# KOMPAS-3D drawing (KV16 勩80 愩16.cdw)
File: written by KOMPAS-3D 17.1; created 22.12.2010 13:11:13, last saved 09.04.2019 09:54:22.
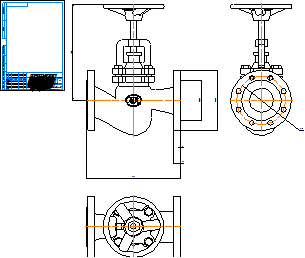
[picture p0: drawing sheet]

Title block, sheet 1: name: KV16 Ду80 Ру16; sheets: 1; sheet format: A4; stored path: \\adlc.lan\data\АДЛ_ПКД\3D-модели\ADL production\Вентили ГРАНВЕНТ\KV16\KOMPAS 2D\KV16 Ду80 Ру16.cdw

Views: Спереди 1
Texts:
  Рама для чертежей
  Лит-Масса-Масштаб
  Материал-Предприятие
  Масштаб
  Изм.
  Лист
  № докум.
  Подп.
  Дата
  Лит.
  Разраб.
  Пров.
  Т.контр.
  Листов
  Внимание! Данный продукт является объектом авторского права ООО «Торговый Дом АДЛ».
  Запрещается изменение, копирование, распространение
  (в том числе путем копирования на другие сайты и ресурсы в Интернете)
  или любое иное использование информации и объектов без предварительного
  согласия правообладателя (ООО «Торговый Дом АДЛ»).
  Н.контр.
  Утв.
  ООО "Торговый дом АДЛ"
  Изменение
  Номер документа
  Подпись
  Обозначение документа
  Наименование изделия
  Масса изделия по ГОСТ 2.109-73
  Порядковый номер листа
  Общее количество листов в документе
  Характер работы, выполненной лицом, подписавшим документ
  Наименование или индекс предприятия, выпускающего документ
  Инв. № подл.
  Подп. и дата
  Взам. инв. №
  Инв. № дубл.
  Инвентарный номер подлинника по ГОСТ 2.501-68
  Подпись принявшего подлинник в отдел технической документации
  Инвентарный номер подлинника, взамен которого выпущен данный подлинник
  Инвентарный номер дубликата по ГОСТ 2.502-68
  Подпись принявшего дубликат в отдел технической документации
  Справ. №
  Перв. примен.
  Обозначение документа, взамен или на основании которого выпущен данный документ
  Обозначение документа, в котором впервые записан данный документ
  Подпись лица, копировавшего чертеж
  Обозначение формата листа
  !Рама для чертежа
Dimensions and other numbers on the sheet: 132; 200; 310; 2; 22; 160; 317; 1:1; 1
